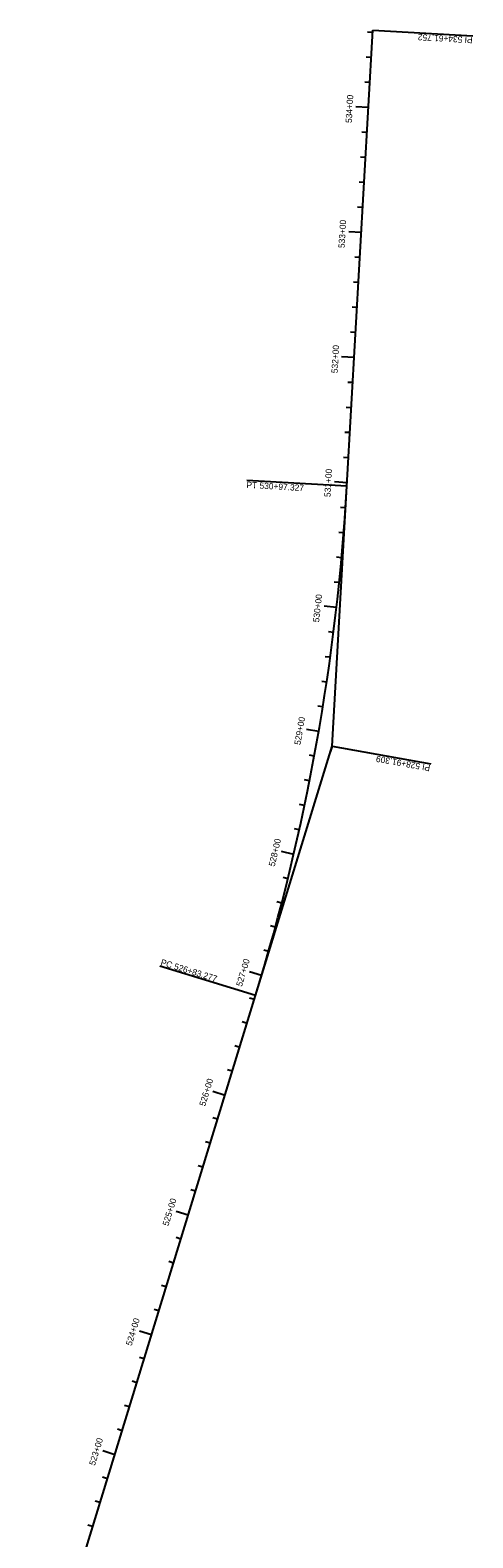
# Model space of a CAD drawing. Extents: x 187748 to 191086, y 249974 to 259749.
# Drawn here: x 190733 to 191086, y 258546 to 259749 of the extents above; entities that cross this region are included whole.
import ezdxf

# ---------------------------------------------------------------- set-up
doc = ezdxf.new("R2010")
doc.units = 0
doc.layers.add('BORDER', color=7, linetype='Continuous')

msp = doc.modelspace()

# ---------------------------------------------------------------- linework, layer by layer
at = {"layer": 'BORDER'}
for p, q in [((190985.9, 259385.3), (191006.5, 259749.1)), ((191006.4, 259747.3), (191002.4, 259747.6)), ((191006.5, 259749.1), (191086.4, 259744.6)), ((191005.3, 259727.4), (191001.3, 259727.6)), ((191004.1, 259707.4), (191000.1, 259707.6)), ((191003, 259687.4), (190993, 259688)), ((191001.9, 259667.5), (190997.9, 259667.7)), ((191000.7, 259647.5), (190996.7, 259647.7)), ((190999.6, 259627.5), (190995.6, 259627.8)), ((190998.5, 259607.6), (190994.5, 259607.8)), ((190997.3, 259587.6), (190987.4, 259588.2)), ((190996.2, 259567.6), (190992.2, 259567.9)), ((190995.1, 259547.7), (190991.1, 259547.9)), ((190993.9, 259527.7), (190990, 259527.9)), ((190992.8, 259507.7), (190988.8, 259508)), ((190991.7, 259487.8), (190981.7, 259488.3)), ((190990.5, 259467.8), (190986.6, 259468)), ((190989.4, 259447.8), (190985.4, 259448)), ((190988.3, 259427.9), (190984.3, 259428.1)), ((190987.2, 259407.9), (190983.2, 259408.1)), ((190985.9, 259385.3), (190906, 259389.8)), ((190986, 259387.9), (190976, 259388.5)), ((190984.8, 259368), (190980.8, 259368.2)), ((190983.3, 259348), (190979.4, 259348.3)), ((190981.7, 259328.1), (190977.7, 259328.4)), ((190979.8, 259308.2), (190975.8, 259308.6)), ((190977.6, 259288.3), (190967.7, 259289.4)), ((190975.2, 259268.4), (190971.3, 259268.9)), ((190972.6, 259248.6), (190968.7, 259249.1)), ((190969.8, 259228.8), (190965.8, 259229.4)), ((190966.7, 259209), (190962.8, 259209.7)), ((190963.4, 259189.3), (190953.6, 259191)), ((190974.1, 259177.6), (190974.4, 259182.5)), ((190959.9, 259169.6), (190956, 259170.4)), ((190974.1, 259177.6), (190972.6, 259172.8)), ((190974.1, 259177.6), (191052.8, 259163.5)), ((190956.1, 259150), (190952.2, 259150.8)), ((190952.2, 259130.4), (190948.2, 259131.2)), ((190947.9, 259110.8), (190944, 259111.7)), ((190943.5, 259091.3), (190933.8, 259093.6)), ((190938.8, 259071.9), (190935, 259072.8)), ((190933.9, 259052.5), (190930.1, 259053.5)), ((190928.8, 259033.2), (190925, 259034.2)), ((190923.5, 259013.9), (190919.6, 259015)), ((190913.1, 258978.7), (190836.6, 259002.1)), ((190917.9, 258994.7), (190908.3, 258997.5)), ((190733.3, 258392.2), (190913.1, 258978.7)), ((190912.1, 258975.5), (190908.3, 258976.7)), ((190906.3, 258956.4), (190902.4, 258957.6)), ((190900.4, 258937.3), (190896.6, 258938.5)), ((190894.5, 258918.2), (190890.7, 258919.3)), ((190888.7, 258899), (190879.1, 258902)), ((190882.8, 258879.9), (190879, 258881.1)), ((190877, 258860.8), (190873.1, 258862)), ((190871.1, 258841.7), (190867.3, 258842.9)), ((190865.2, 258822.6), (190861.4, 258823.7)), ((190859.4, 258803.4), (190849.8, 258806.4)), ((190853.5, 258784.3), (190849.7, 258785.5)), ((190847.6, 258765.2), (190843.8, 258766.4)), ((190841.8, 258746.1), (190838, 258747.2)), ((190835.9, 258727), (190832.1, 258728.1)), ((190830, 258707.8), (190820.5, 258710.8)), ((190824.2, 258688.7), (190820.4, 258689.9)), ((190818.3, 258669.6), (190814.5, 258670.8)), ((190812.5, 258650.5), (190808.6, 258651.6)), ((190806.6, 258631.3), (190802.8, 258632.5)), ((190800.7, 258612.2), (190791.2, 258615.2)), ((190794.9, 258593.1), (190791, 258594.3)), ((190789, 258574), (190785.2, 258575.2)), ((190783.1, 258554.9), (190779.3, 258556))]:
    msp.add_line(p, q, dxfattribs=at)
msp.add_lwpolyline([(190913.1, 258978.7), (190974.1, 259177.6), (190985.9, 259385.3)], dxfattribs=at)
msp.add_arc((189269.7, 259482.6), 1718.9, 342.9522, 356.7536, dxfattribs=at)

# ---------------------------------------------------------------- texts
for s, rotation, p in [('PI 534+61.752', 176.7537, (191086.3, 259743.6)), ('534+00', 86.7537, (190989.8, 259674.9)), ('533+00', 86.7537, (190984.1, 259575.1)), ('532+00', 86.7537, (190978.5, 259475.2)), ('531+00', 86.7537, (190972.8, 259376.4)), ('PT 530+97.327', 356.7537, (190905.7, 259383.8)), ('530+00', 83.5095, (190963.7, 259276.3)), ('529+00', 80.1762, (190948.8, 259178.4)), ('PI 528+91.309', 169.8529, (191052.7, 259162.5)), ('528+00', 76.8429, (190928.3, 259081.3)), ('PC 526+83.277', 342.9522, (190836.9, 259003.1)), ('527+00', 73.5096, (190902.2, 258985.5)), ('526+00', 72.9522, (190872.8, 258890)), ('525+00', 72.9522, (190843.5, 258794.4)), ('524+00', 72.9522, (190814.2, 258698.8)), ('523+00', 72.9522, (190784.9, 258603.2))]:
    msp.add_text(s, height=5, rotation=rotation, dxfattribs=at).set_placement(p)

doc.saveas('drawing.dxf')
